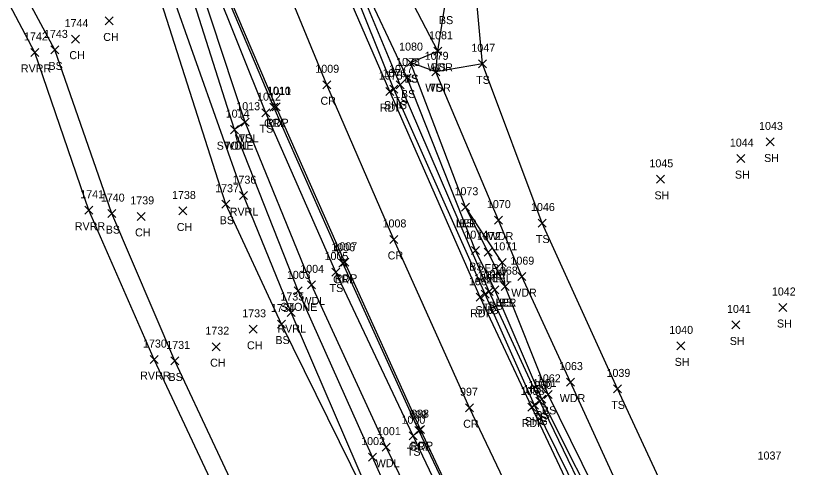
# Model space of a CAD drawing. Extents: x 1545627 to 1546562, y 571176 to 576667.
# Drawn here: x 1546177.9 to 1546373.5, y 571592.1 to 571704.9 of the extents above; entities that cross this region are included whole.
import ezdxf

# ---------------------------------------------------------------- set-up
doc = ezdxf.new("R2010")
doc.units = 0
for name, color, linetype in [('L_A', 7, 'Continuous'), ('L_I', 7, 'Continuous'), ('L_TIC', 7, 'Continuous'), ('LARO', 7, 'Continuous'), ('LASF', 7, 'Continuous'), ('LAWA', 7, 'Continuous'), ('LAWE', 7, 'Continuous'), ('LELB', 7, 'Continuous'), ('P_A', 7, 'Continuous'), ('P_I', 7, 'Continuous'), ('P_TIC', 7, 'Continuous'), ('PET', 7, 'Continuous'), ('PRC', 7, 'Continuous'), ('PSU', 7, 'Continuous'), ('R_A', 7, 'Continuous'), ('R_I', 7, 'Continuous'), ('R_TIC', 7, 'Continuous'), ('RGR', 7, 'Continuous')]:
    doc.layers.add(name, color=color, linetype=linetype)

msp = doc.modelspace()

# ---------------------------------------------------------------- linework, layer by layer
at = {"layer": 'L_TIC'}
for points in [[(1546200.27, 571702.61), (1546202.27, 571704.61)], [(1546202.27, 571702.61), (1546200.27, 571704.61)], [(1546191.79, 571698.06), (1546193.79, 571700.06)], [(1546193.79, 571698.06), (1546191.79, 571700.06)], [(1546186.64, 571695.37), (1546188.64, 571697.37)], [(1546188.64, 571695.37), (1546186.64, 571697.37)], [(1546181.65, 571694.75), (1546183.65, 571696.75)], [(1546183.65, 571694.75), (1546181.65, 571696.75)], [(1546282.41, 571695.03), (1546284.41, 571697.03)], [(1546284.41, 571695.03), (1546282.41, 571697.03)], [(1546282.41, 571695.03), (1546284.41, 571697.03)], [(1546284.41, 571695.03), (1546282.41, 571697.03)], [(1546275.57, 571692.2), (1546277.57, 571694.2)], [(1546277.57, 571692.2), (1546275.57, 571694.2)], [(1546275.57, 571692.2), (1546277.57, 571694.2)], [(1546277.57, 571692.2), (1546275.57, 571694.2)], [(1546293.54, 571691.89), (1546295.54, 571693.89)], [(1546295.54, 571691.89), (1546293.54, 571693.89)], [(1546293.54, 571691.89), (1546295.54, 571693.89)], [(1546295.54, 571691.89), (1546293.54, 571693.89)], [(1546281.89, 571689.9), (1546283.89, 571691.9)], [(1546283.89, 571689.9), (1546281.89, 571691.9)], [(1546281.89, 571689.9), (1546283.89, 571691.9)], [(1546283.89, 571689.9), (1546281.89, 571691.9)], [(1546274.73, 571688.36), (1546276.73, 571690.36)], [(1546276.73, 571688.36), (1546274.73, 571690.36)], [(1546272.97, 571686.64), (1546274.97, 571688.64)], [(1546274.97, 571686.64), (1546272.97, 571688.64)], [(1546239.42, 571679.68), (1546241.42, 571681.68)], [(1546241.42, 571679.68), (1546239.42, 571681.68)], [(1546234.21, 571677.3), (1546236.21, 571679.3)], [(1546236.21, 571677.3), (1546234.21, 571679.3)], [(1546234.21, 571677.3), (1546236.21, 571679.3)], [(1546236.21, 571677.3), (1546234.21, 571679.3)], [(1546231.58, 571675.44), (1546233.58, 571677.44)], [(1546233.58, 571675.44), (1546231.58, 571677.44)], [(1546231.58, 571675.44), (1546233.58, 571677.44)], [(1546233.58, 571675.44), (1546231.58, 571677.44)], [(1546365.44, 571672.37), (1546367.44, 571674.37)], [(1546367.44, 571672.37), (1546365.44, 571674.37)], [(1546358.14, 571668.21), (1546360.14, 571670.21)], [(1546360.14, 571668.21), (1546358.14, 571670.21)], [(1546338.04, 571663.03), (1546340.04, 571665.03)], [(1546340.04, 571663.03), (1546338.04, 571665.03)], [(1546233.82, 571658.95), (1546235.82, 571660.95)], [(1546235.82, 571658.95), (1546233.82, 571660.95)], [(1546229.42, 571656.81), (1546231.42, 571658.81)], [(1546231.42, 571656.81), (1546229.42, 571658.81)], [(1546195.14, 571655.31), (1546197.14, 571657.31)], [(1546197.14, 571655.31), (1546195.14, 571657.31)], [(1546200.94, 571654.46), (1546202.94, 571656.46)], [(1546202.94, 571654.46), (1546200.94, 571656.46)], [(1546218.65, 571655.12), (1546220.65, 571657.12)], [(1546220.65, 571655.12), (1546218.65, 571657.12)], [(1546289.32, 571656.05), (1546291.32, 571658.05)], [(1546291.32, 571656.05), (1546289.32, 571658.05)], [(1546289.32, 571656.05), (1546291.32, 571658.05)], [(1546291.32, 571656.05), (1546289.32, 571658.05)], [(1546289.32, 571656.05), (1546291.32, 571658.05)], [(1546291.32, 571656.05), (1546289.32, 571658.05)], [(1546208.23, 571653.77), (1546210.23, 571655.77)], [(1546210.23, 571653.77), (1546208.23, 571655.77)], [(1546297.51, 571652.83), (1546299.51, 571654.83)], [(1546299.51, 571652.83), (1546297.51, 571654.83)], [(1546308.49, 571652.11), (1546310.49, 571654.11)], [(1546310.49, 571652.11), (1546308.49, 571654.11)], [(1546291.79, 571645.22), (1546293.79, 571647.22)], [(1546293.79, 571645.22), (1546291.79, 571647.22)], [(1546294.94, 571644.83), (1546296.94, 571646.83)], [(1546296.94, 571644.83), (1546294.94, 571646.83)], [(1546298.48, 571642.28), (1546300.48, 571644.28)], [(1546300.48, 571642.28), (1546298.48, 571644.28)], [(1546256.92, 571639.86), (1546258.92, 571641.86)], [(1546258.92, 571639.86), (1546256.92, 571641.86)], [(1546303.35, 571638.71), (1546305.35, 571640.71)], [(1546305.35, 571638.71), (1546303.35, 571640.71)], [(1546247.5, 571635.16), (1546249.5, 571637.16)], [(1546249.5, 571635.16), (1546247.5, 571637.16)], [(1546250.85, 571636.66), (1546252.85, 571638.66)], [(1546252.85, 571636.66), (1546250.85, 571638.66)], [(1546295.21, 571634.99), (1546297.21, 571636.99)], [(1546297.21, 571634.99), (1546295.21, 571636.99)], [(1546296.64, 571635.43), (1546298.64, 571637.43)], [(1546298.64, 571635.43), (1546296.64, 571637.43)], [(1546299.23, 571636.22), (1546301.23, 571638.22)], [(1546301.23, 571636.22), (1546299.23, 571638.22)], [(1546299.23, 571636.22), (1546301.23, 571638.22)], [(1546301.23, 571636.22), (1546299.23, 571638.22)], [(1546299.23, 571636.22), (1546301.23, 571638.22)], [(1546301.23, 571636.22), (1546299.23, 571638.22)], [(1546368.64, 571631), (1546370.64, 571633)], [(1546370.64, 571631), (1546368.64, 571633)], [(1546245.73, 571629.75), (1546247.73, 571631.75)], [(1546247.73, 571629.75), (1546245.73, 571631.75)], [(1546236.19, 571625.55), (1546238.19, 571627.55)], [(1546238.19, 571625.55), (1546236.19, 571627.55)], [(1546243.35, 571626.87), (1546245.35, 571628.87)], [(1546245.35, 571626.87), (1546243.35, 571628.87)], [(1546356.86, 571626.64), (1546358.86, 571628.64)], [(1546358.86, 571626.64), (1546356.86, 571628.64)], [(1546226.99, 571621.21), (1546228.99, 571623.21)], [(1546228.99, 571621.21), (1546226.99, 571623.21)], [(1546343.09, 571621.41), (1546345.09, 571623.41)], [(1546345.09, 571621.41), (1546343.09, 571623.41)], [(1546211.48, 571617.99), (1546213.48, 571619.99)], [(1546213.48, 571617.99), (1546211.48, 571619.99)], [(1546216.63, 571617.65), (1546218.63, 571619.65)], [(1546218.63, 571617.65), (1546216.63, 571619.65)], [(1546315.5, 571612.36), (1546317.5, 571614.36)], [(1546317.5, 571612.36), (1546315.5, 571614.36)], [(1546309.96, 571609.3), (1546311.96, 571611.3)], [(1546311.96, 571609.3), (1546309.96, 571611.3)], [(1546327.32, 571610.66), (1546329.32, 571612.66)], [(1546329.32, 571610.66), (1546327.32, 571612.66)], [(1546307.89, 571607.63), (1546309.89, 571609.63)], [(1546309.89, 571607.63), (1546307.89, 571609.63)], [(1546308.35, 571608.13), (1546310.35, 571610.13)], [(1546310.35, 571608.13), (1546308.35, 571610.13)], [(1546276.23, 571598.95), (1546278.23, 571600.95)], [(1546278.23, 571598.95), (1546276.23, 571600.95)], [(1546269.45, 571596.1), (1546271.45, 571598.1)], [(1546271.45, 571596.1), (1546269.45, 571598.1)], [(1546266.07, 571593.62), (1546268.07, 571595.62)], [(1546268.07, 571593.62), (1546266.07, 571595.62)]]:
    msp.add_lwpolyline(points, dxfattribs=at)
at = {"layer": 'LARO'}
for points in [[(1546300.23, 571637.22), (1546299.48, 571643.28), (1546290.32, 571657.05)], [(1546300.23, 571637.22), (1546295.94, 571645.83), (1546290.32, 571657.05)]]:
    msp.add_lwpolyline(points, dxfattribs=at)
at = {"layer": 'LASF'}
msp.add_lwpolyline([(1546302.63, 571514.7), (1546284.96, 571554.64), (1546267.07, 571594.62), (1546248.5, 571636.16), (1546232.58, 571676.44), (1546221.39, 571711.67), (1546206.12, 571743.52), (1546187.79, 571777.34), (1546173.69, 571810.79)], dxfattribs=at)
at = {"layer": 'LAWA'}
for points in [[(1546353.68, 571538.67), (1546333.05, 571577.3), (1546316.5, 571613.36), (1546304.35, 571639.71), (1546298.51, 571653.83), (1546282.89, 571690.9), (1546283.41, 571696.03), (1546272.32, 571717.42), (1546269.96, 571722.04), (1546267.97, 571732.31), (1546261.81, 571747.15), (1546257.75, 571780.48), (1546250.52, 571795.52), (1546235.49, 571816.76), (1546225.64, 571844.56)], [(1546312.75, 571517.59), (1546290.07, 571556.93), (1546270.45, 571597.1), (1546251.85, 571637.66), (1546235.21, 571678.3), (1546232.58, 571676.44)]]:
    msp.add_lwpolyline(points, dxfattribs=at)
at = {"layer": 'LAWE'}
for points in [[(1546291.68, 571509.09), (1546276, 571554.51), (1546265.8, 571586.47), (1546246.73, 571630.75), (1546234.82, 571659.95), (1546216.56, 571711.52), (1546198.01, 571746.58), (1546176.48, 571789.7), (1546167.29, 571818.28), (1546149.73, 571861.96), (1546132.38, 571905.18), (1546121.26, 571957.17), (1546118.8, 571996.68)], [(1546258.96, 571503.98), (1546247.25, 571543.2), (1546232.25, 571576.91), (1546212.48, 571618.99), (1546196.14, 571656.31), (1546182.65, 571695.75), (1546160.61, 571737.45), (1546138.23, 571773.59), (1546130.29, 571811.19), (1546113.32, 571843.26), (1546096.49, 571860.06), (1546088.58, 571875.57), (1546087.04, 571900.32), (1546085.16, 571952.92), (1546079.44, 571966.95), (1546077.79, 571985.49)]]:
    msp.add_lwpolyline(points, dxfattribs=at)
at = {"layer": 'LELB'}
for points in [[(1546347.4, 571535.24), (1546326.62, 571574.77), (1546309.35, 571609.13), (1546297.64, 571636.43), (1546292.79, 571646.22), (1546275.73, 571689.36), (1546263.63, 571715.11), (1546250.32, 571751.35), (1546233.4, 571797.16), (1546220.82, 571841.74), (1546218.61, 571853), (1546198.39, 571897.18), (1546185.1, 571947.88), (1546175.65, 571989.22), (1546174.94, 572003.26), (1546174.78, 572026.81), (1546167.55, 572047.44), (1546164.76, 572064.39), (1546160.42, 572092.89), (1546150.12, 572129.23)], [(1546346.37, 571534.64), (1546325.48, 571574.25), (1546308.89, 571608.63), (1546296.21, 571635.99), (1546273.97, 571687.64), (1546262.69, 571714.72), (1546248.75, 571750.39), (1546231.96, 571796.63), (1546217.3, 571838.7), (1546210.36, 571854.99), (1546196.65, 571897), (1546182.1, 571946.81), (1546169.64, 571995.56), (1546168.24, 572028.13), (1546158.04, 572044.97), (1546148.17, 572086.53), (1546140.64, 572120.6)], [(1546316.39, 571519.99), (1546295.99, 571560.57), (1546277.23, 571599.95), (1546257.92, 571640.86), (1546240.42, 571680.68), (1546227.25, 571713.56), (1546212.6, 571746.96), (1546199.61, 571780.81), (1546186.37, 571815.41), (1546174.93, 571851.82), (1546162.84, 571891.38), (1546151.94, 571927.81), (1546142.36, 571967.05), (1546132.26, 572008.4), (1546126.74, 572032.68), (1546118.89, 572071.99), (1546116.87, 572083.76)], [(1546289.09, 571508.47), (1546272.41, 571554.88), (1546264.55, 571586.76), (1546244.35, 571627.87), (1546230.42, 571657.81), (1546213.76, 571710.05), (1546197.12, 571744.15), (1546174.21, 571790.13), (1546160.91, 571814.7), (1546145.83, 571859.21), (1546131.62, 571904.03), (1546118.44, 571956.95), (1546115.97, 571995.99), (1546108.78, 572035.92), (1546103.73, 572068.58)], [(1546290.32, 571657.05), (1546276.57, 571693.2), (1546283.41, 571696.03), (1546285.22, 571707.81), (1546280.59, 571717.61), (1546272.32, 571717.42), (1546265, 571715.53), (1546255.38, 571753.56), (1546251.92, 571771.02), (1546251.67, 571784.62), (1546239.77, 571800.02), (1546225.64, 571844.56), (1546223.57, 571853.75), (1546206.91, 571899.08), (1546191.55, 571950.78), (1546183.98, 571991.38)], [(1546264.48, 571501.32), (1546248.81, 571543.43), (1546237.8, 571575.68), (1546217.63, 571618.65), (1546201.94, 571655.46), (1546187.64, 571696.37), (1546165.93, 571736.68), (1546143.43, 571776.5), (1546133.35, 571812.72), (1546115.39, 571843.89), (1546097.02, 571861.67), (1546090.93, 571875.32), (1546090.22, 571893.11)], [(1546235.21, 571678.3), (1546223.98, 571712.48), (1546207.43, 571744.29)], [(1546362.29, 571543.58), (1546342.98, 571580.07), (1546328.32, 571611.66), (1546309.49, 571653.11), (1546294.54, 571692.89), (1546292.56, 571714.76), (1546278.25, 571725.92)], [(1546294.54, 571692.89), (1546282.89, 571690.9), (1546276.57, 571693.2)], [(1546349.57, 571537), (1546327.97, 571575.78), (1546310.96, 571610.3), (1546300.23, 571637.22)]]:
    msp.add_lwpolyline(points, dxfattribs=at)
at = {"layer": 'P_TIC'}
for points in [[(1546254.63, 571686.66), (1546256.63, 571688.66)], [(1546256.63, 571686.66), (1546254.63, 571688.66)], [(1546270.4, 571684.96), (1546272.4, 571686.96)], [(1546272.4, 571684.96), (1546270.4, 571686.96)], [(1546271.39, 571685.56), (1546273.39, 571687.56)], [(1546273.39, 571685.56), (1546271.39, 571687.56)], [(1546241.96, 571681.18), (1546243.96, 571683.18)], [(1546243.96, 571681.18), (1546241.96, 571683.18)], [(1546271.42, 571648.01), (1546273.42, 571650.01)], [(1546273.42, 571648.01), (1546271.42, 571650.01)], [(1546259.13, 571642.3), (1546261.13, 571644.3)], [(1546261.13, 571642.3), (1546259.13, 571644.3)], [(1546292.98, 571633.56), (1546294.98, 571635.56)], [(1546294.98, 571633.56), (1546292.98, 571635.56)], [(1546294.25, 571634.34), (1546296.25, 571636.34)], [(1546296.25, 571634.34), (1546294.25, 571636.34)], [(1546290.29, 571605.95), (1546292.29, 571607.95)], [(1546292.29, 571605.95), (1546290.29, 571607.95)], [(1546305.85, 571606.13), (1546307.85, 571608.13)], [(1546307.85, 571606.13), (1546305.85, 571608.13)], [(1546306.57, 571606.61), (1546308.57, 571608.61)], [(1546308.57, 571606.61), (1546306.57, 571608.61)], [(1546278.07, 571600.48), (1546280.07, 571602.48)], [(1546280.07, 571600.48), (1546278.07, 571602.48)]]:
    msp.add_lwpolyline(points, dxfattribs=at)
at = {"layer": 'PET'}
for points in [[(1546536.21, 571181.01), (1546508.17, 571223.67), (1546475.69, 571271.66), (1546448.41, 571311.32), (1546419.18, 571354.19), (1546394.92, 571390.86), (1546367.78, 571434.2), (1546346.92, 571469.65), (1546328.81, 571502.75), (1546318.67, 571520.99), (1546297.7, 571561.78), (1546279.07, 571601.48), (1546260.13, 571643.3), (1546242.96, 571682.18), (1546229.29, 571714.28), (1546215.95, 571747.93), (1546202.6, 571782.08), (1546189.82, 571816.62), (1546177.58, 571852.76), (1546165.76, 571891.53), (1546154.55, 571928.81), (1546144.5, 571967.92), (1546134.66, 572009.13)], [(1546559.08, 571194.5), (1546529.75, 571240.45), (1546499.79, 571284.88), (1546470.8, 571327.72), (1546443.13, 571367.68), (1546417.68, 571406.9), (1546392.95, 571446.31), (1546370.2, 571483.99), (1546352.76, 571515), (1546343.41, 571532.43), (1546322.94, 571573.04), (1546306.85, 571607.13), (1546293.98, 571634.56), (1546271.4, 571685.96), (1546259.46, 571713.47), (1546245.43, 571748.53), (1546227.67, 571795.22), (1546213.04, 571834.88), (1546205.18, 571857.76), (1546192.7, 571896.53), (1546178.72, 571945.47), (1546165.66, 571996.1)]]:
    msp.add_lwpolyline(points, dxfattribs=at)
at = {"layer": 'PRC'}
msp.add_lwpolyline([(1546547.34, 571187.72), (1546518.74, 571231.86), (1546487.31, 571278.43), (1546459.33, 571318.89), (1546430.57, 571360.77), (1546405.96, 571398.26), (1546380.25, 571440.1), (1546358.53, 571476.99), (1546340.41, 571508.44), (1546330.22, 571526.95), (1546310.11, 571567.47), (1546291.29, 571606.95), (1546272.42, 571649.01), (1546255.63, 571687.66), (1546242.53, 571719.45), (1546229.29, 571753.1), (1546216.08, 571786.74), (1546203.35, 571821.01), (1546191.26, 571856.19), (1546178.74, 571896.13), (1546167.5, 571932.69), (1546157.43, 571971.54), (1546147.89, 572011.79)], dxfattribs=at)
at = {"layer": 'PSU'}
msp.add_lwpolyline([(1546344.91, 571533.75), (1546324.24, 571573.75), (1546307.57, 571607.61), (1546295.25, 571635.34), (1546272.39, 571686.56), (1546261.3, 571714.23), (1546246.81, 571749.3), (1546229.82, 571796.03), (1546214.93, 571836.38), (1546208.22, 571856.11), (1546194.62, 571896.65), (1546180.08, 571945.81), (1546167.4, 571995.97), (1546161.66, 572024.84), (1546155.58, 572044.54)], dxfattribs=at)
at = {"layer": 'R_TIC'}
for points in [[(1546241.43, 571681.09), (1546243.43, 571683.09)], [(1546243.43, 571681.09), (1546241.43, 571683.09)], [(1546258.67, 571642.05), (1546260.67, 571644.05)], [(1546260.67, 571642.05), (1546258.67, 571644.05)], [(1546277.61, 571600.26), (1546279.61, 571602.26)], [(1546279.61, 571600.26), (1546277.61, 571602.26)]]:
    msp.add_lwpolyline(points, dxfattribs=at)
at = {"layer": 'RGR'}
msp.add_lwpolyline([(1546318.09, 571520.89), (1546297.39, 571561.7), (1546278.61, 571601.26), (1546259.67, 571643.05), (1546242.43, 571682.09), (1546228.78, 571714.21), (1546215.19, 571747.99), (1546202.24, 571781.5), (1546189.29, 571816.51), (1546177.18, 571852.71), (1546165.01, 571891.35), (1546154.15, 571928.78), (1546143.68, 571967.8), (1546133.91, 572008.79), (1546128.63, 572033), (1546121.13, 572073.3), (1546118.95, 572085.97)], dxfattribs=at)

# ---------------------------------------------------------------- texts
at = {"layer": 'L_A'}
for s, p in [('BS', (1546283.66, 571702.81)), ('CH', (1546199.76, 571698.61)), ('CH', (1546191.28, 571694.06)), ('RVRR', (1546179.17, 571690.75)), ('BS', (1546186.08, 571691.37)), ('WDR', (1546280.77, 571691.03)), ('BS', (1546281.85, 571691.03)), ('TS', (1546274.98, 571688.2)), ('BS', (1546275.01, 571688.2)), ('TS', (1546292.95, 571687.89)), ('TS', (1546292.95, 571687.89)), ('WDR', (1546280.25, 571685.9)), ('TS', (1546281.3, 571685.9)), ('BS', (1546274.17, 571684.36)), ('TS', (1546272.38, 571682.64)), ('TS', (1546238.83, 571675.68)), ('WDL', (1546232.63, 571673.3)), ('TS', (1546233.62, 571673.3)), ('STONE', (1546228.12, 571671.44)), ('WDL', (1546230, 571671.44)), ('SH', (1546364.93, 571668.37)), ('SH', (1546357.63, 571664.21)), ('SH', (1546337.53, 571659.03)), ('RVRL', (1546231.38, 571654.95)), ('BS', (1546228.86, 571652.81)), ('RVRR', (1546192.65, 571651.31)), ('BS', (1546200.38, 571650.46)), ('CH', (1546218.14, 571651.12)), ('LER', (1546287.9, 571652.05)), ('LEL', (1546287.96, 571652.05)), ('BS', (1546288.76, 571652.05)), ('CH', (1546207.72, 571649.77)), ('WDR', (1546295.87, 571648.83)), ('TS', (1546307.9, 571648.11)), ('BS', (1546291.23, 571641.22)), ('LER', (1546293.52, 571640.83)), ('LEL', (1546297.11, 571638.28)), ('TS', (1546256.33, 571635.86)), ('WDR', (1546301.72, 571634.71)), ('STONE', (1546244.05, 571631.16)), ('WDL', (1546249.27, 571632.66)), ('TS', (1546294.62, 571630.99)), ('BS', (1546296.08, 571631.43)), ('LER', (1546297.81, 571632.22)), ('LEL', (1546297.87, 571632.22)), ('BS', (1546298.67, 571632.22)), ('SH', (1546368.13, 571627)), ('RVRL', (1546243.29, 571625.75)), ('CH', (1546235.68, 571621.55)), ('BS', (1546242.79, 571622.87)), ('SH', (1546356.35, 571622.64)), ('CH', (1546226.48, 571617.21)), ('SH', (1546342.58, 571617.41)), ('RVRR', (1546208.99, 571613.99)), ('BS', (1546216.07, 571613.65)), ('WDR', (1546313.86, 571608.36)), ('TS', (1546326.73, 571606.66)), ('TS', (1546307.3, 571603.63)), ('BS', (1546307.79, 571604.13)), ('BS', (1546309.4, 571605.3)), ('TS', (1546275.64, 571594.95)), ('WDL', (1546267.87, 571592.1))]:
    msp.add_text(s, height=2, dxfattribs=at).set_placement(p)
at = {"layer": 'L_I'}
for s, p in [('1744', (1546190.1, 571702.06)), ('1743', (1546184.95, 571699.37)), ('1742', (1546179.96, 571698.75)), ('1081', (1546281.2, 571699.03)), ('1081', (1546281.2, 571699.03)), ('1080', (1546273.71, 571696.2)), ('1080', (1546273.71, 571696.2)), ('1047', (1546291.77, 571695.89)), ('1047', (1546291.77, 571695.89)), ('1079', (1546280.11, 571693.9)), ('1079', (1546280.11, 571693.9)), ('1078', (1546272.96, 571692.36)), ('1077', (1546271.2, 571690.64)), ('1012', (1546238.21, 571683.68)), ('1013', (1546233.01, 571681.3)), ('1013', (1546233.01, 571681.3)), ('1014', (1546230.37, 571679.44)), ('1014', (1546230.37, 571679.44)), ('1043', (1546363.67, 571676.37)), ('1044', (1546356.37, 571672.21)), ('1045', (1546336.27, 571667.03)), ('1736', (1546232.07, 571662.95)), ('1737', (1546227.73, 571660.81)), ('1741', (1546194.02, 571659.31)), ('1740', (1546199.16, 571658.46)), ('1738', (1546216.95, 571659.12)), ('1073', (1546287.55, 571660.05)), ('1073', (1546287.55, 571660.05)), ('1073', (1546287.55, 571660.05)), ('1739', (1546206.53, 571657.77)), ('1070', (1546295.65, 571656.83)), ('1046', (1546306.67, 571656.11)), ('1074', (1546290.02, 571649.22)), ('1072', (1546293.17, 571648.83)), ('1071', (1546297.27, 571646.28)), ('1005', (1546255.07, 571643.86)), ('1069', (1546301.53, 571642.71)), ('1004', (1546249, 571640.66)), ('1003', (1546245.65, 571639.16)), ('1066', (1546293.34, 571638.99)), ('1067', (1546294.82, 571639.43)), ('1068', (1546297.41, 571640.22)), ('1068', (1546297.41, 571640.22)), ('1068', (1546297.41, 571640.22)), ('1042', (1546366.87, 571635)), ('1735', (1546244.03, 571633.75)), ('1734', (1546241.66, 571630.87)), ('1733', (1546234.5, 571629.55)), ('1041', (1546355.66, 571630.64)), ('1732', (1546225.29, 571625.21)), ('1040', (1546341.23, 571625.41)), ('1730', (1546209.7, 571621.99)), ('1731', (1546215.51, 571621.65)), ('1063', (1546313.68, 571616.36)), ('1062', (1546308.14, 571613.3)), ('1039', (1546325.54, 571614.66)), ('1060', (1546305.99, 571611.63)), ('1061', (1546307.1, 571612.13)), ('1000', (1546274.3, 571602.95)), ('1001', (1546268.17, 571600.1)), ('1002', (1546264.22, 571597.62)), ('1037', (1546363.3, 571594.01))]:
    msp.add_text(s, height=2, dxfattribs=at).set_placement(p)
at = {"layer": 'P_A'}
for s, p in [('CR', (1546254.06, 571682.66)), ('RDP', (1546268.89, 571680.96)), ('SHG', (1546269.93, 571681.56)), ('RDP', (1546240.45, 571677.18)), ('CR', (1546270.85, 571644.01)), ('RDP', (1546257.62, 571638.3)), ('RDP', (1546291.47, 571629.56)), ('SHG', (1546292.79, 571630.34)), ('CR', (1546289.72, 571601.95)), ('RDP', (1546304.34, 571602.13)), ('SHG', (1546305.1, 571602.61)), ('RDP', (1546276.56, 571596.48))]:
    msp.add_text(s, height=2, dxfattribs=at).set_placement(p)
at = {"layer": 'P_I'}
for s, p in [('1009', (1546252.77, 571690.66)), ('1076', (1546269.56, 571689.56)), ('1075', (1546268.63, 571688.96)), ('1010', (1546240.67, 571685.18)), ('1008', (1546269.57, 571652.01)), ('1007', (1546257.28, 571646.3)), ('1064', (1546291.16, 571637.56)), ('1065', (1546292.44, 571638.34)), ('997', (1546288.93, 571609.95)), ('1058', (1546304.08, 571610.13)), ('1059', (1546304.79, 571610.61)), ('998', (1546276.71, 571604.48))]:
    msp.add_text(s, height=2, dxfattribs=at).set_placement(p)
at = {"layer": 'R_A'}
for p in [(1546239.97, 571677.09), (1546257.21, 571638.05), (1546276.15, 571596.26)]:
    msp.add_text('GRL', height=2, dxfattribs=at).set_placement(p)
at = {"layer": 'R_I'}
for s, p in [('1011', (1546240.79, 571685.09)), ('1006', (1546256.76, 571646.05)), ('999', (1546276.24, 571604.26))]:
    msp.add_text(s, height=2, dxfattribs=at).set_placement(p)

doc.saveas('drawing.dxf')
